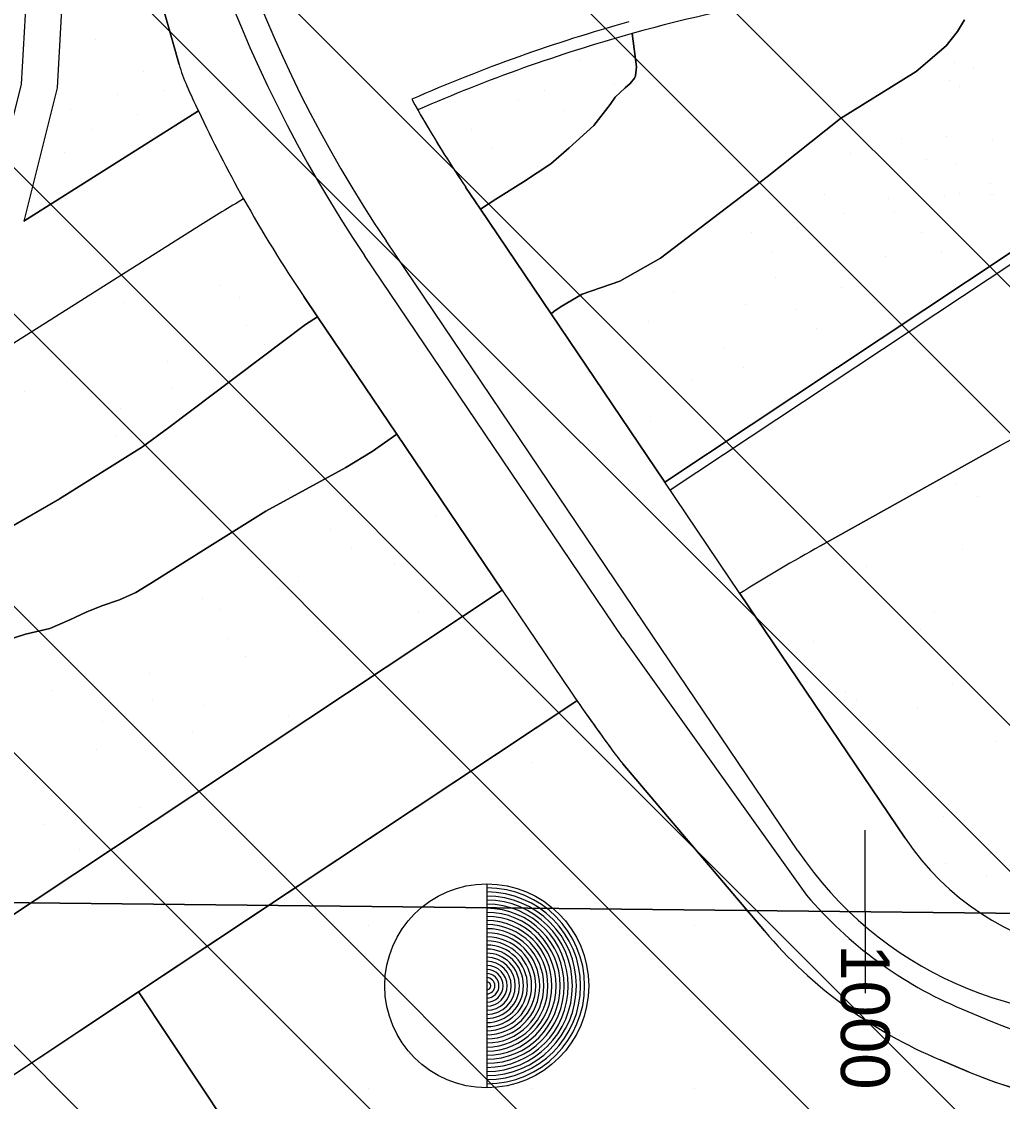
# Model space of a CAD drawing. Extents: x 419109 to 421295, y 4452223 to 4457798.
# Drawn here: x 420870.4 to 421021.1, y 4454973.1 to 4455138.9 of the extents above; entities that cross this region are included whole.
import ezdxf

# ---------------------------------------------------------------- set-up
doc = ezdxf.new("R2010")
doc.units = 0
for name, color, linetype in [('0_PLAN_ONAMA_İLAVE_SINIRI', 7, 'Continuous'), ('ADAKENARI', 7, 'Continuous'), ('Default', 7, 'Continuous'), ('LJ_SEMBOL', 7, 'Continuous'), ('PAFTALAMA', 7, 'Continuous'), ('PL_AYA_PARK_DINLENME', 7, 'Continuous'), ('PL_K_YONETIM', 7, 'Continuous'), ('PL_TA_K_DERE', 7, 'Continuous'), ('SN_TR_SIVILASMA', 7, 'Continuous'), ('TR_PARKALANI', 7, 'Continuous'), ('TR_TALIISMERK', 7, 'Continuous'), ('TRFAT_KHA', 7, 'Continuous')]:
    doc.layers.add(name, color=color, linetype=linetype)

# ---------------------------------------------------------------- blocks, each defined once
blk = doc.blocks.new('POINT_DISPLAY')
at = {"layer": 'Default'}
blk.add_line((0, 0), (0, 0), dxfattribs=at)

msp = doc.modelspace()

# ---------------------------------------------------------------- linework, layer by layer
at = {"layer": '0_PLAN_ONAMA_İLAVE_SINIRI'}
for p, q in [((420870.42, 4455129.31), (420876.65, 4455243.37)), ((420859.78, 4455086.9), (420870.42, 4455129.31))]:
    msp.add_line(p, q, dxfattribs=at)
at = {"layer": 'ADAKENARI'}
for p, q in [((420879.82, 4455200.57), (420875.9, 4455128.72)), ((420887.16, 4455158.74), (420894.61, 4455132.33)), ((421014.14, 4455137.41), (421015.22, 4455139.19)), ((420964.85, 4455131.95), (420964.18, 4455137.06)), ((421012.44, 4455135.18), (421014.14, 4455137.41)), ((421014.14, 4455137.41), (421014.14, 4455137.41)), ((421007.83, 4455131.25), (421012.44, 4455135.18)), ((421012.44, 4455135.18), (421012.44, 4455135.18)), ((420964.71, 4455130.59), (420964.85, 4455131.95)), ((420964.85, 4455131.95), (420964.85, 4455131.95)), ((420963.9, 4455129.42), (420964.56, 4455130.21)), ((420964.56, 4455130.21), (420964.71, 4455130.59)), ((420964.56, 4455130.21), (420964.56, 4455130.21)), ((420964.71, 4455130.59), (420964.71, 4455130.59)), ((420996.2, 4455124.03), (421007.83, 4455131.25)), ((421007.83, 4455131.25), (421007.83, 4455131.25)), ((420875.9, 4455128.72), (420870.76, 4455108.25)), ((420961.6, 4455127.31), (420963.12, 4455128.74)), ((420963.12, 4455128.74), (420963.9, 4455129.42)), ((420963.12, 4455128.74), (420963.12, 4455128.74)), ((420963.9, 4455129.42), (420963.9, 4455129.42)), ((420960.82, 4455126.18), (420961.6, 4455127.31)), ((420961.6, 4455127.31), (420961.6, 4455127.31)), ((420897.57, 4455125.18), (420870.76, 4455108.25)), ((420958.32, 4455122.95), (420960.82, 4455126.18)), ((420960.82, 4455126.18), (420960.82, 4455126.18)), ((420984.94, 4455115.05), (420996.2, 4455124.03)), ((420996.2, 4455124.03), (420996.2, 4455124.03)), ((420954.5, 4455119.54), (420958.32, 4455122.95)), ((420958.32, 4455122.95), (420958.32, 4455122.95)), ((420951.71, 4455117.04), (420954.5, 4455119.54)), ((420954.5, 4455119.54), (420954.5, 4455119.54)), ((420947.51, 4455114.31), (420951.71, 4455117.04)), ((420951.71, 4455117.04), (420951.71, 4455117.04)), ((420968.57, 4455102.56), (420984.94, 4455115.05)), ((420984.94, 4455115.05), (420984.94, 4455115.05)), ((420940.91, 4455110.1), (420938.62, 4455113.49)), ((420943.28, 4455111.62), (420947.51, 4455114.31)), ((420947.51, 4455114.31), (420947.51, 4455114.31)), ((420940.91, 4455110.1), (420943.28, 4455111.62)), ((420943.28, 4455111.62), (420943.28, 4455111.62)), ((420940.91, 4455110.1), (420940.91, 4455110.1)), ((420951.75, 4455094.04), (420940.91, 4455110.1)), ((420897.9, 4455107.65), (420722.47, 4454996.86)), ((420966.01, 4455046.56), (420926.4, 4455105.23)), ((421022.27, 4455103.39), (420969.21, 4455068.18)), ((420962.7, 4455044.33), (420923.08, 4455102.99)), ((420962.29, 4455099.05), (420968.57, 4455102.56)), ((420968.57, 4455102.56), (420968.57, 4455102.56)), ((421023.1, 4455102.14), (420970.05, 4455066.94)), ((420956.52, 4455097.04), (420962.29, 4455099.05)), ((420913.76, 4455096.7), (420915.88, 4455093.55)), ((420915.88, 4455093.55), (420928.05, 4455075.54)), ((420969.21, 4455068.18), (420951.75, 4455094.04)), ((420893.04, 4455076.56), (420914.03, 4455092.37)), ((420928.05, 4455075.54), (420944.22, 4455051.59)), ((420993.1, 4455058.38), (421020.57, 4455073.73)), ((420980.75, 4455051.09), (420969.21, 4455068.18)), ((420944.22, 4455051.59), (420782.75, 4454944.44)), ((420944.22, 4455051.59), (420953.37, 4455038.03)), ((421006.13, 4455013.5), (420980.75, 4455051.09)), ((420989.63, 4455011.58), (420966.01, 4455046.56)), ((420962.7, 4455044.33), (420990.98, 4455004.77)), ((420832.46, 4454952.83), (420955.71, 4455034.62)), ((420962.75, 4455024.94), (420984.5, 4454999.28)), ((420888.38, 4454989.93), (420912.25, 4454953.96)), ((421014.78, 4454987.31), (421019.27, 4454985.42)), ((421011.49, 4454979.48), (421015.97, 4454977.59))]:
    msp.add_line(p, q, dxfattribs=at)
for points in [[(420951.75, 4455094.04), (420952.15, 4455094.39), (420953.27, 4455095.17), (420956.52, 4455097.04)], [(420914.03, 4455092.37), (420915.88, 4455093.55)], [(420803.3, 4455020.41), (420808.04, 4455023.29), (420811.67, 4455025.83), (420818.64, 4455032.34), (420825.56, 4455037.63), (420828.82, 4455039.53), (420842.5, 4455046.46), (420858.56, 4455055.43), (420876.22, 4455065.62), (420888.97, 4455073.58), (420893.04, 4455076.56)], [(420866.66, 4455043.46), (420871.01, 4455044.84), (420874.74, 4455045.72), (420877.84, 4455047.02), (420880.35, 4455048.23), (420882.75, 4455049.21), (420885.46, 4455050.12), (420887.94, 4455051.26), (420890.23, 4455052.63), (420899.31, 4455058.34), (420907.91, 4455063.75), (420920.2, 4455070.45), (420924.24, 4455072.88), (420928.05, 4455075.54)]]:
    msp.add_lwpolyline(points, dxfattribs=at)
for centre, radius, start, end in [((421090.5, 4455216.03), 202, 183.9272, 214.0256), ((421090.5, 4455216.03), 198, 183.9272, 214.0256), ((421031.39, 4454896.27), 250, 93.1308, 105.5937), ((421031.39, 4454896.27), 251.87, 105.5937, 113.6525), ((421031.39, 4454896.27), 250, 105.5937, 113.6096), ((420917.71, 4455138.84), 24, 195.7341, 204.0712), ((421090.5, 4455216.03), 213.25, 204.0712, 205.2143), ((421090.5, 4455216.03), 183.25, 209.0729, 214.0256), ((421090.5, 4455216.03), 213.25, 205.2143, 209.2933), ((421031.39, 4454896.27), 250, 120.4954, 122.2723), ((421090.5, 4455216.03), 213.25, 209.2933, 214.0256), ((421040.94, 4455037), 42, 214.0254, 119.0131), ((421138.44, 4454798.23), 298, 119.1916, 121.9489), ((421041, 4455037.03), 64.5, 247.1692, 5.7757), ((421041, 4455037.03), 56, 247.1692, 5.7757), ((421223.56, 4455220.45), 326, 214.0256, 216.5842), ((420981.06, 4455040.45), 24, 216.5842, 220.2889), ((421037.49, 4455043.9), 57.75, 214.0256, 277.7243), ((421039.42, 4455045.83), 63.5, 220.2889, 247.1692), ((421039.42, 4455045.83), 72, 220.2889, 247.1692)]:
    msp.add_arc(centre, radius, start, end, dxfattribs=at)
at = {"layer": 'LJ_SEMBOL'}
msp.add_line((420941.86, 4455006.5), (420941.86, 4454975.18), dxfattribs=at)
msp.add_circle((420941.86, 4454990.84), 15.66, dxfattribs=at)
for radius in [15.04, 14.41, 13.78, 13.16, 12.53, 11.9, 11.28, 10.65, 10.02, 9.4, 8.77, 8.14, 7.52, 6.89, 6.26, 5.64, 5.01, 4.39, 3.76, 3.13, 2.51, 1.88, 1.25, 0.627]:
    msp.add_arc((420941.86, 4454990.84), radius, 270, 90, dxfattribs=at)
at = {"layer": 'PAFTALAMA'}
for p, q in [((421266.41, 4454999.4), (419138.44, 4455021.89)), ((421000, 4455002.22), (421000, 4455014.72)), ((421000, 4455002.22), (421000, 4455002.22)), ((421000, 4455002.22), (421000, 4454989.72))]:
    msp.add_line(p, q, dxfattribs=at)
msp.add_lwpolyline([(419168.18, 4457798.01), (419138.44, 4455021.89), (421266.41, 4454999.4), (421295.36, 4457775.52)], dxfattribs=at)
at = {"layer": 'PL_AYA_PARK_DINLENME'}
for p, q in [((420879.82, 4455200.57), (420875.9, 4455128.72)), ((420894.61, 4455132.33), (420887.16, 4455158.74)), ((421015.22, 4455139.19), (421014.14, 4455137.41)), ((420964.85, 4455131.95), (420964.18, 4455137.06)), ((421014.14, 4455137.41), (421012.44, 4455135.18)), ((421012.44, 4455135.18), (421007.83, 4455131.25)), ((420964.71, 4455130.59), (420964.85, 4455131.95)), ((420963.9, 4455129.42), (420964.56, 4455130.21)), ((420964.56, 4455130.21), (420964.71, 4455130.59)), ((421007.83, 4455131.25), (420996.2, 4455124.03)), ((420875.9, 4455128.72), (420870.76, 4455108.25)), ((420961.6, 4455127.31), (420963.12, 4455128.74)), ((420963.12, 4455128.74), (420963.9, 4455129.42)), ((420960.82, 4455126.18), (420961.6, 4455127.31)), ((420870.76, 4455108.25), (420897.57, 4455125.18)), ((420958.32, 4455122.95), (420960.82, 4455126.18)), ((420996.2, 4455124.03), (420984.94, 4455115.05)), ((420954.5, 4455119.54), (420958.32, 4455122.95)), ((420951.71, 4455117.04), (420954.5, 4455119.54)), ((420947.51, 4455114.31), (420951.71, 4455117.04)), ((420984.94, 4455115.05), (420968.57, 4455102.56)), ((420938.62, 4455113.49), (420940.91, 4455110.1)), ((420943.28, 4455111.62), (420947.51, 4455114.31)), ((420940.91, 4455110.1), (420943.28, 4455111.62)), ((420897.9, 4455107.65), (420722.47, 4454996.86)), ((420969.21, 4455068.18), (421022.27, 4455103.39)), ((420968.57, 4455102.56), (420962.29, 4455099.05)), ((420962.29, 4455099.05), (420956.52, 4455097.04)), ((420915.88, 4455093.55), (420913.76, 4455096.7)), ((420914.03, 4455092.37), (420915.88, 4455093.55)), ((420951.75, 4455094.04), (420969.21, 4455068.18)), ((420893.04, 4455076.56), (420914.03, 4455092.37)), ((420944.22, 4455051.59), (420928.05, 4455075.54)), ((421020.57, 4455073.73), (420993.1, 4455058.38)), ((420782.75, 4454944.44), (420944.22, 4455051.59)), ((420980.75, 4455051.09), (421006.13, 4455013.5)), ((420888.38, 4454989.93), (420832.46, 4454952.83)), ((420912.25, 4454953.96), (420888.38, 4454989.93))]:
    msp.add_line(p, q, dxfattribs=at)
for points in [[(420964.18, 4455137.06), (420964.18, 4455137.07)], [(420956.52, 4455097.04), (420953.27, 4455095.17), (420952.15, 4455094.39), (420951.75, 4455094.04)], [(420803.3, 4455020.41), (420808.04, 4455023.29), (420811.67, 4455025.83), (420818.64, 4455032.34), (420825.56, 4455037.63), (420828.82, 4455039.53), (420842.5, 4455046.46), (420858.56, 4455055.43), (420876.22, 4455065.62), (420888.97, 4455073.58), (420893.04, 4455076.56)], [(420928.05, 4455075.54), (420924.24, 4455072.88), (420920.2, 4455070.45), (420907.91, 4455063.75), (420899.31, 4455058.34), (420890.23, 4455052.63), (420887.94, 4455051.26), (420885.46, 4455050.12), (420882.75, 4455049.21), (420880.35, 4455048.23), (420877.84, 4455047.02), (420874.74, 4455045.72), (420871.01, 4455044.84), (420866.66, 4455043.46)]]:
    msp.add_lwpolyline(points, dxfattribs=at)
for centre, radius, start, end in [((421031.39, 4454896.27), 250, 105.5937, 113.6096), ((420917.71, 4455138.84), 24, 195.7341, 204.0712), ((421090.5, 4455216.03), 213.25, 204.0712, 205.2143), ((421090.5, 4455216.03), 183.25, 209.6603, 214.0256), ((421031.39, 4454896.27), 250, 120.4954, 122.2723), ((421090.5, 4455216.03), 213.25, 209.2933, 214.0256), ((421040.94, 4455037), 42, 214.0254, 119.0131), ((421138.44, 4454798.23), 298, 119.1916, 121.9489)]:
    msp.add_arc(centre, radius, start, end, dxfattribs=at)
at = {"layer": 'PL_K_YONETIM'}
for p, q in [((420955.71, 4455034.62), (420888.38, 4454989.93)), ((420984.5, 4454999.28), (420962.75, 4455024.94)), ((420888.38, 4454989.93), (420912.25, 4454953.96)), ((421015.97, 4454977.59), (421011.49, 4454979.48))]:
    msp.add_line(p, q, dxfattribs=at)
for centre, radius, start, end in [((421223.56, 4455220.45), 326, 214.7529, 216.5842), ((420981.06, 4455040.45), 24, 216.5842, 220.2889), ((421039.42, 4455045.83), 72, 220.2889, 247.1692), ((421041, 4455037.03), 64.5, 247.1692, 263.1405)]:
    msp.add_arc(centre, radius, start, end, dxfattribs=at)
at = {"layer": 'PL_TA_K_DERE'}
for p, q in [((421014.14, 4455137.41), (421015.22, 4455139.19)), ((420964.18, 4455137.07), (420964.18, 4455137.06)), ((420964.18, 4455137.06), (420964.85, 4455131.95)), ((421012.44, 4455135.18), (421014.14, 4455137.41)), ((421007.83, 4455131.25), (421012.44, 4455135.18)), ((420964.85, 4455131.95), (420964.71, 4455130.59)), ((420964.56, 4455130.21), (420963.9, 4455129.42)), ((420964.71, 4455130.59), (420964.56, 4455130.21)), ((420996.2, 4455124.03), (421007.83, 4455131.25)), ((420963.12, 4455128.74), (420961.6, 4455127.31)), ((420963.9, 4455129.42), (420963.12, 4455128.74)), ((420961.6, 4455127.31), (420960.82, 4455126.18)), ((420960.82, 4455126.18), (420958.32, 4455122.95)), ((420984.94, 4455115.05), (420996.2, 4455124.03)), ((420958.32, 4455122.95), (420954.5, 4455119.54)), ((420954.5, 4455119.54), (420951.71, 4455117.04)), ((420951.71, 4455117.04), (420947.51, 4455114.31)), ((420968.57, 4455102.56), (420984.94, 4455115.05)), ((420947.51, 4455114.31), (420943.28, 4455111.62)), ((420943.28, 4455111.62), (420940.91, 4455110.1)), ((420940.91, 4455110.1), (420951.75, 4455094.04)), ((420962.29, 4455099.05), (420968.57, 4455102.56)), ((420956.52, 4455097.04), (420962.29, 4455099.05)), ((420915.88, 4455093.55), (420914.03, 4455092.37)), ((420928.05, 4455075.54), (420915.88, 4455093.55)), ((420914.03, 4455092.37), (420893.04, 4455076.56)), ((420924.24, 4455072.88), (420928.05, 4455075.54)), ((420920.2, 4455070.45), (420924.24, 4455072.88)), ((420876.22, 4455065.62), (420858.56, 4455055.43)), ((420890.23, 4455052.63), (420899.31, 4455058.34)), ((420887.94, 4455051.26), (420890.23, 4455052.63)), ((420885.46, 4455050.12), (420887.94, 4455051.26))]:
    msp.add_line(p, q, dxfattribs=at)
for points in [[(420951.75, 4455094.04), (420952.15, 4455094.39), (420953.27, 4455095.17), (420956.52, 4455097.04)], [(420893.04, 4455076.56), (420888.97, 4455073.58), (420876.22, 4455065.62)], [(420899.31, 4455058.34), (420907.91, 4455063.75), (420920.2, 4455070.45)], [(420880.35, 4455048.23), (420882.75, 4455049.21), (420885.46, 4455050.12)], [(420863.52, 4455042.08), (420866.66, 4455043.46), (420871.01, 4455044.84), (420874.74, 4455045.72), (420877.84, 4455047.02), (420880.35, 4455048.23)]]:
    msp.add_lwpolyline(points, dxfattribs=at)
msp.add_arc((421031.39, 4454896.27), 250, 93.1308, 105.5937, dxfattribs=at)
at = {"layer": 'SN_TR_SIVILASMA'}
for p, q in [((421119.44, 4455000.96), (420129.33, 4455991.06)), ((421096.75, 4455001.2), (420145.11, 4455952.83)), ((421051.37, 4455001.68), (420175.05, 4455878)), ((421028.68, 4455001.92), (420190.02, 4455840.58)), ((420983.3, 4455002.39), (420204.76, 4455780.94)), ((420960.61, 4455002.63), (420211.17, 4455752.07)), ((420915.23, 4455003.11), (420224, 4455694.34)), ((420892.54, 4455003.35), (420230.42, 4455665.47)), ((421262.13, 4454588.86), (420847.16, 4455003.83)), ((421262.59, 4454633.3), (420892.54, 4455003.35)), ((421262.82, 4454655.52), (420915.23, 4455003.11)), ((421263.29, 4454699.96), (420960.61, 4455002.63)), ((421263.52, 4454722.18), (420983.3, 4455002.39))]:
    msp.add_line(p, q, dxfattribs=at)
at = {"layer": 'TR_TALIISMERK'}
for p, q in [((420888.38, 4454989.93), (420832.46, 4454952.83)), ((420912.25, 4454953.96), (420888.38, 4454989.93))]:
    msp.add_line(p, q, dxfattribs=at)
at = {"layer": 'TRFAT_KHA'}
for p, q in [((420948.74, 4455025.14), (420948.74, 4455025.14)), ((420923.74, 4455000.14), (420923.74, 4455000.14)), ((420948.74, 4455000.14), (420948.74, 4455000.14)), ((420973.74, 4455000.14), (420973.74, 4455000.14)), ((420898.74, 4454975.14), (420898.74, 4454975.14)), ((420923.74, 4454975.14), (420923.74, 4454975.14)), ((420948.74, 4454975.14), (420948.74, 4454975.14)), ((420973.74, 4454975.14), (420973.74, 4454975.14)), ((420998.74, 4454975.14), (420998.74, 4454975.14))]:
    msp.add_line(p, q, dxfattribs=at)

# ---------------------------------------------------------------- block references
at = {"layer": 'TR_PARKALANI', "xscale": 0.1, "yscale": 0.10000000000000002}
for p in [(420881.84, 4455136.09), (420956.04, 4455133.11), (421013.7, 4455132.62), (421016.67, 4455131.7), (420889.16, 4455131.27), (421012.88, 4455129.84), (420892.27, 4455128.28), (420950.75, 4455128.3), (420961.55, 4455129.34), (421014.52, 4455129.01), (420885.12, 4455127.68), (420946.78, 4455126.73), (420877.98, 4455125.36), (420953.87, 4455125.31), (420888.23, 4455124.68), (420932, 4455124.13), (420881.1, 4455122.36), (420939.58, 4455122.39), (421005.58, 4455121.03), (421012.55, 4455121.29), (421019.54, 4455120.86), (420877.05, 4455118.76), (420942.69, 4455119.39), (420997.77, 4455118.68), (420949.69, 4455116.72), (421009.37, 4455117.68), (421014.06, 4455116.93), (420938.66, 4455115.15), (421019.2, 4455114.07), (420993.69, 4455112.42), (421003.56, 4455111.75), (421012.24, 4455112.05), (421014.52, 4455112.47), (421019.21, 4455112.31), (421019.76, 4455112.42), (420996.8, 4455109.42), (421004.43, 4455109.7), (420982.51, 4455106.5), (420989.66, 4455107.1), (421008.58, 4455106.5), (420985.62, 4455103.5), (421011.69, 4455103.5), (421003.03, 4455102.83), (420901.01, 4455098.36), (420986.18, 4455099.58), (420903.91, 4455096.61), (420970.54, 4455097.26), (420996.32, 4455098.12), (420886.24, 4455095.75), (420981.55, 4455095.52), (420989.42, 4455094.75), (420904.96, 4455092.24), (420966.78, 4455092.91), (420992.53, 4455091.75), (420907.67, 4455089.38), (420978.24, 4455088.83), (420892.9, 4455086.77), (420981.35, 4455085.84), (420878.12, 4455084.17), (420973.44, 4455083.93), (420870.9, 4455082.12), (420893.47, 4455082.6), (420885.67, 4455079.52), (420967.07, 4455077.57), (420884.78, 4455075.19), (421008.23, 4455066.87), (421014.04, 4455067.86), (421017.31, 4455066), (420921.01, 4455064.53), (420934.05, 4455063.08), (420917.9, 4455060.97), (420921.02, 4455057.97), (421014.89, 4455057.89), (420927.67, 4455055.55), (420996.66, 4455055.69), (421000.12, 4455055.29), (420906.73, 4455055.05), (420909.84, 4455052.05), (420912.9, 4455052.95), (420985.35, 4455052.68), (420898.13, 4455050.34), (420901.03, 4455048.6), (420931.45, 4455048.31), (421010.56, 4455048.16), (420915.81, 4455045.99), (421006.78, 4455046.31), (421008.41, 4455045.48), (420902.08, 4455044.23), (420919.56, 4455043.97), (420992.01, 4455043.71), (420904.79, 4455041.36), (420890.02, 4455038.76), (421013.44, 4455037.33), (420875.24, 4455036.15), (420996.92, 4455035.84), (420890.58, 4455034.59), (420898.43, 4455033.82), (420998.67, 4455034.73), (420911.45, 4455032.38), (421007.96, 4455033.39), (420882.79, 4455031.5), (420896.68, 4455029.78), (420881.9, 4455027.17), (421020.1, 4455028.35), (421005.33, 4455025.75), (420888.56, 4455018.19), (420873.79, 4455015.59), (421011.99, 4455016.77), (420881.69, 4455014.07), (420879.31, 4455011.81), (421019.26, 4455011.09), (421012.37, 4455009.64), (421018.65, 4455007.79)]:
    msp.add_blockref('POINT_DISPLAY', p, dxfattribs=at)

# ---------------------------------------------------------------- texts
at = {"layer": 'PAFTALAMA'}
msp.add_text('1000', height=7.5, rotation=270, dxfattribs=at).set_placement((420996.25, 4454997.22))

doc.saveas('drawing.dxf')
